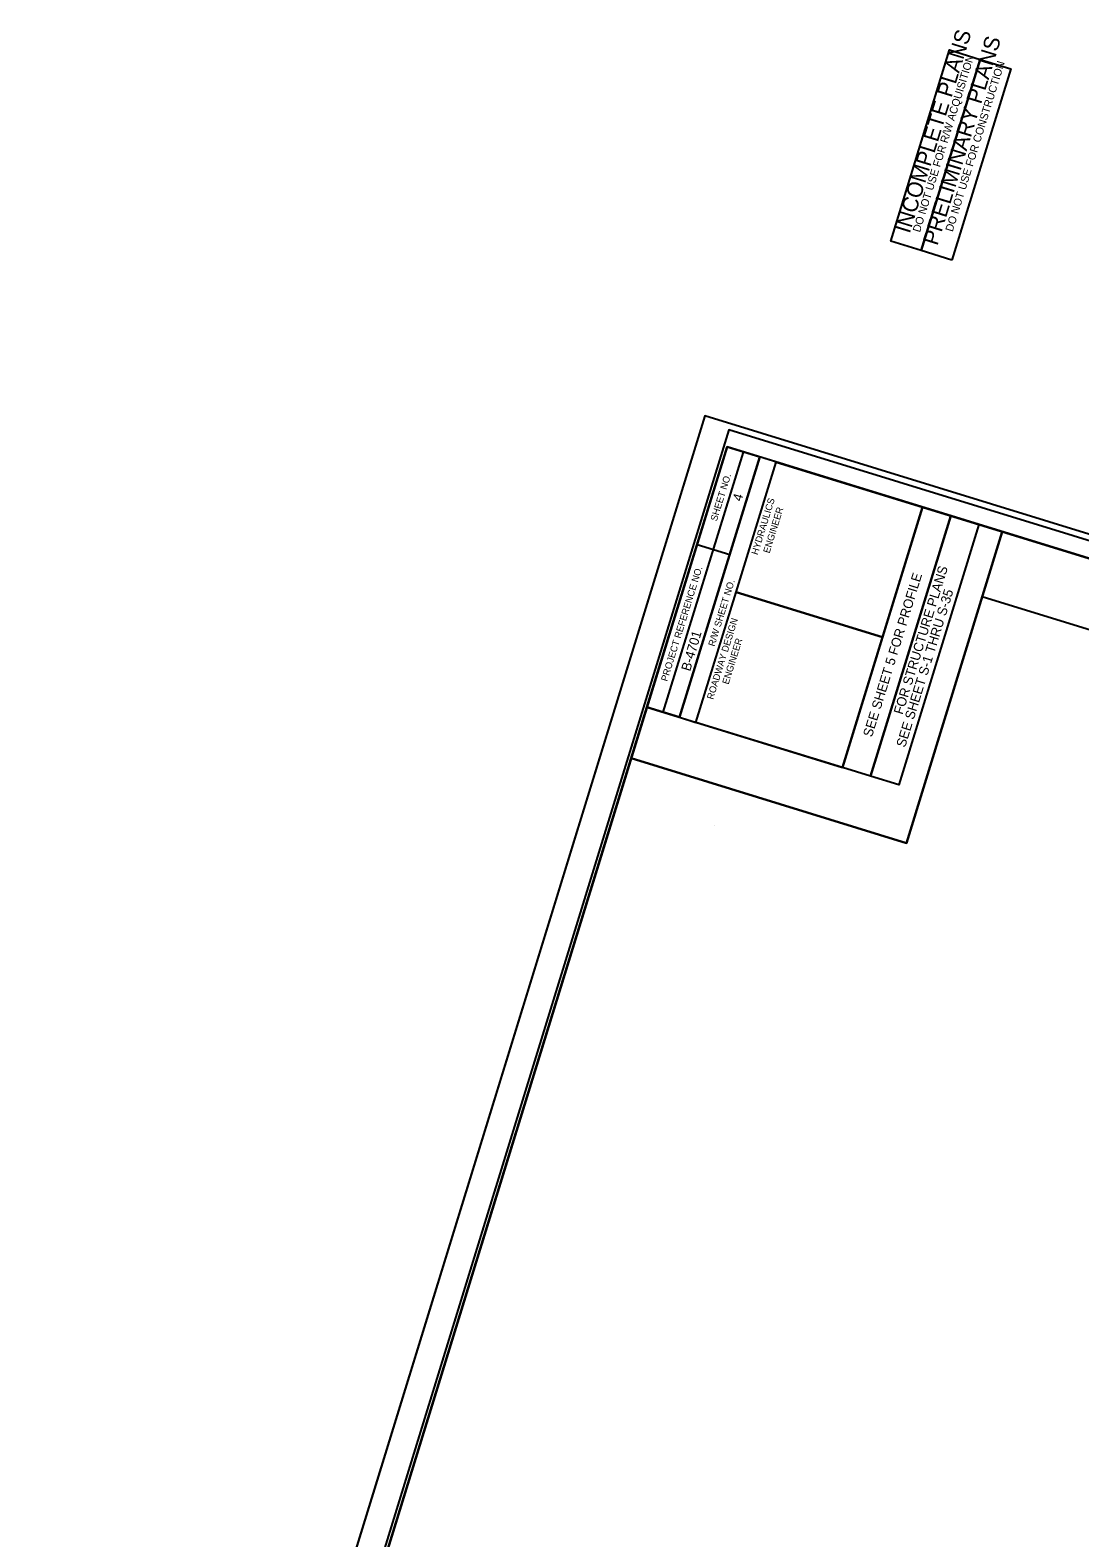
# Model space of a CAD drawing. Extents: x 1347957 to 1349499, y 1028289 to 1030503.
# Drawn here: x 1347957 to 1348728, y 1029396 to 1030503 of the extents above; entities that cross this region are included whole.
import ezdxf

# ---------------------------------------------------------------- set-up
doc = ezdxf.new("R2010")
doc.units = 0
for name, color, linetype in [('Prop Dimension', 7, 'Continuous'), ('Prop DSN Text', 7, 'Continuous'), ('Sheet Clip Boundary CELL', 7, 'Continuous'), ('Sheet Cutting Line CELL', 7, 'Continuous'), ('Sheet Layout Plan Border', 7, 'Continuous'), ('Sheet North Arrow Point CELL', 7, 'Continuous'), ('Sheet Plan CELL', 7, 'Continuous'), ('Sheet Plan Layout CELL', 7, 'Continuous'), ('Sheet Plot Border Inside CELL', 7, 'Continuous'), ('Sheet Plot Border Outside CELL', 7, 'Continuous'), ('Sheet Sticker Incomplete CELL', 7, 'Continuous'), ('Sheet Sticker Preliminary CELL', 7, 'Continuous')]:
    doc.layers.add(name, color=color, linetype=linetype)

msp = doc.modelspace()

# ---------------------------------------------------------------- linework, layer by layer
at = {"layer": 'Prop Dimension'}
for points in [[(1348553.6, 1029961.8), (1348612.4, 1030153), (1348633.2, 1030146.6), (1348574.3, 1029955.4)], [(1348574.3, 1029955.4), (1348633.2, 1030146.6), (1348653.9, 1030140.2), (1348595, 1029949)]]:
    msp.add_lwpolyline(points, close=True, dxfattribs=at)
at = {"layer": 'Sheet Clip Boundary CELL'}
msp.add_lwpolyline([(1349045.8, 1028502.3), (1349457.8, 1029840.3), (1348656.4, 1030087.1), (1348600.7, 1029906.2), (1348398.6, 1029968.5), (1348042.3, 1028811.4)], close=True, dxfattribs=at)
at = {"layer": 'Sheet Cutting Line CELL'}
msp.add_line((1348452.5, 1030220), (1347957.1, 1028611.1), dxfattribs=at)
at = {"layer": 'Sheet Layout Plan Border'}
msp.add_lwpolyline([(1349045.8, 1028502.3), (1349457.8, 1029840.3), (1348656.4, 1030087.1), (1348600.7, 1029906.2), (1348398.6, 1029968.5), (1348042.3, 1028811.4)], close=True, dxfattribs=at)
at = {"layer": 'Sheet North Arrow Point CELL'}
msp.add_line((1348459.8, 1029919.4), (1348459.8, 1029919.4), dxfattribs=at)
at = {"layer": 'Sheet Plan CELL'}
for p, q in [((1348422.1, 1030002.3), (1348481, 1030193.4)), ((1348434.1, 1029998.6), (1348493, 1030189.8)), ((1348434.1, 1029998.6), (1348493, 1030189.8)), ((1348447, 1030125.4), (1348470.9, 1030118.1)), ((1348475.5, 1030090.5), (1348583, 1030057.4)), ((1348434.1, 1029998.6), (1348446, 1029994.9))]:
    msp.add_line(p, q, dxfattribs=at)
for points in [[(1348469, 1030197.2), (1348027.5, 1028763.6), (1349031, 1028454.5), (1349472.5, 1029888.1)], [(1348410.1, 1030006), (1348469, 1030197.2), (1348493, 1030189.8), (1348434.1, 1029998.6)], [(1348475.5, 1030090.5), (1348504.9, 1030186.1), (1348612.4, 1030153), (1348583, 1030057.4)], [(1349031, 1028454.5), (1348027.6, 1028763.5), (1348410.1, 1030006), (1348553.6, 1029961.8), (1348612.4, 1030153), (1349472.5, 1029888.1)], [(1348446, 1029994.9), (1348475.5, 1030090.5), (1348583, 1030057.4), (1348553.6, 1029961.8)]]:
    msp.add_lwpolyline(points, close=True, dxfattribs=at)
at = {"layer": 'Sheet Plan Layout CELL'}
for points in [[(1348600.7, 1029906.2), (1348671.1, 1030134.9), (1348469, 1030197.2), (1348398.6, 1029968.5)], [(1348027.6, 1028763.5), (1349031, 1028454.5), (1349472.5, 1029888.1), (1348671.1, 1030134.9), (1348600.7, 1029906.2), (1348398.6, 1029968.5)]]:
    msp.add_lwpolyline(points, close=True, dxfattribs=at)
at = {"layer": 'Sheet Plot Border Inside CELL'}
msp.add_lwpolyline([(1348988.3, 1028307.1), (1349478.6, 1029899.3), (1348470.3, 1030209.8), (1347980, 1028617.6)], close=True, dxfattribs=at)
at = {"layer": 'Sheet Plot Border Outside CELL'}
msp.add_lwpolyline([(1349003.6, 1028288.8), (1349499, 1029897.7), (1348452.5, 1030220), (1347957.1, 1028611.1)], close=True, dxfattribs=at)
at = {"layer": 'Sheet Sticker Incomplete CELL'}
msp.add_lwpolyline([(1348611.6, 1030341.4), (1348589.1, 1030348.3), (1348632.4, 1030488.8), (1348654.9, 1030481.8)], close=True, dxfattribs=at)
at = {"layer": 'Sheet Sticker Preliminary CELL'}
msp.add_lwpolyline([(1348634.1, 1030334.4), (1348611.6, 1030341.4), (1348654.9, 1030481.8), (1348677.3, 1030474.9)], close=True, dxfattribs=at)

# ---------------------------------------------------------------- texts
at = {"layer": 'Prop DSN Text'}
for s, rotation, p in [('4', 73.5959, (1348479.5, 1030156.7)), ('FOR STRUCTURE PLANS', 72.8458, (1348597.8, 1030000.2)), ('SEE SHEET 5 FOR PROFILE', 72.8458, (1348575.3, 1029983.6)), ('SEE SHEET S-1 THRU S-35', 72.8458, (1348599.7, 1029976.1)), ('B-4701', 73.5959, (1348441.8, 1030032))]:
    msp.add_text(s, height=7, rotation=rotation, dxfattribs=at).set_placement(p)
at = {"layer": 'Sheet Plan CELL'}
for s, p in [('SHEET NO.', (1348461.4, 1030142.3)), ('HYDRAULICS', (1348491.4, 1030117.5)), ('ENGINEER', (1348500.1, 1030118.7)), ('PROJECT REFERENCE NO.', (1348425, 1030024.6)), ('R/W SHEET NO.', (1348459.7, 1030050.3)), ('ROADWAY DESIGN', (1348458.7, 1030011.3)), ('ENGINEER', (1348470, 1030022.4))]:
    msp.add_text(s, height=5, rotation=72.8834, dxfattribs=at).set_placement(p)
at = {"layer": 'Sheet Sticker Incomplete CELL'}
for s, height, p in [('INCOMPLETE PLANS', 11.52, (1348603, 1030353.4)), ('DO NOT USE FOR R/W ACQUISITION', 5.76, (1348610.6, 1030354.4))]:
    msp.add_text(s, height=height, rotation=72.8834, dxfattribs=at).set_placement(p)
at = {"layer": 'Sheet Sticker Preliminary CELL'}
for s, height, p in [('PRELIMINARY PLANS', 11.52, (1348623.4, 1030344.5)), ('DO NOT USE FOR CONSTRUCTION', 5.76, (1348634.6, 1030354.8))]:
    msp.add_text(s, height=height, rotation=72.8834, dxfattribs=at).set_placement(p)

doc.saveas('drawing.dxf')
